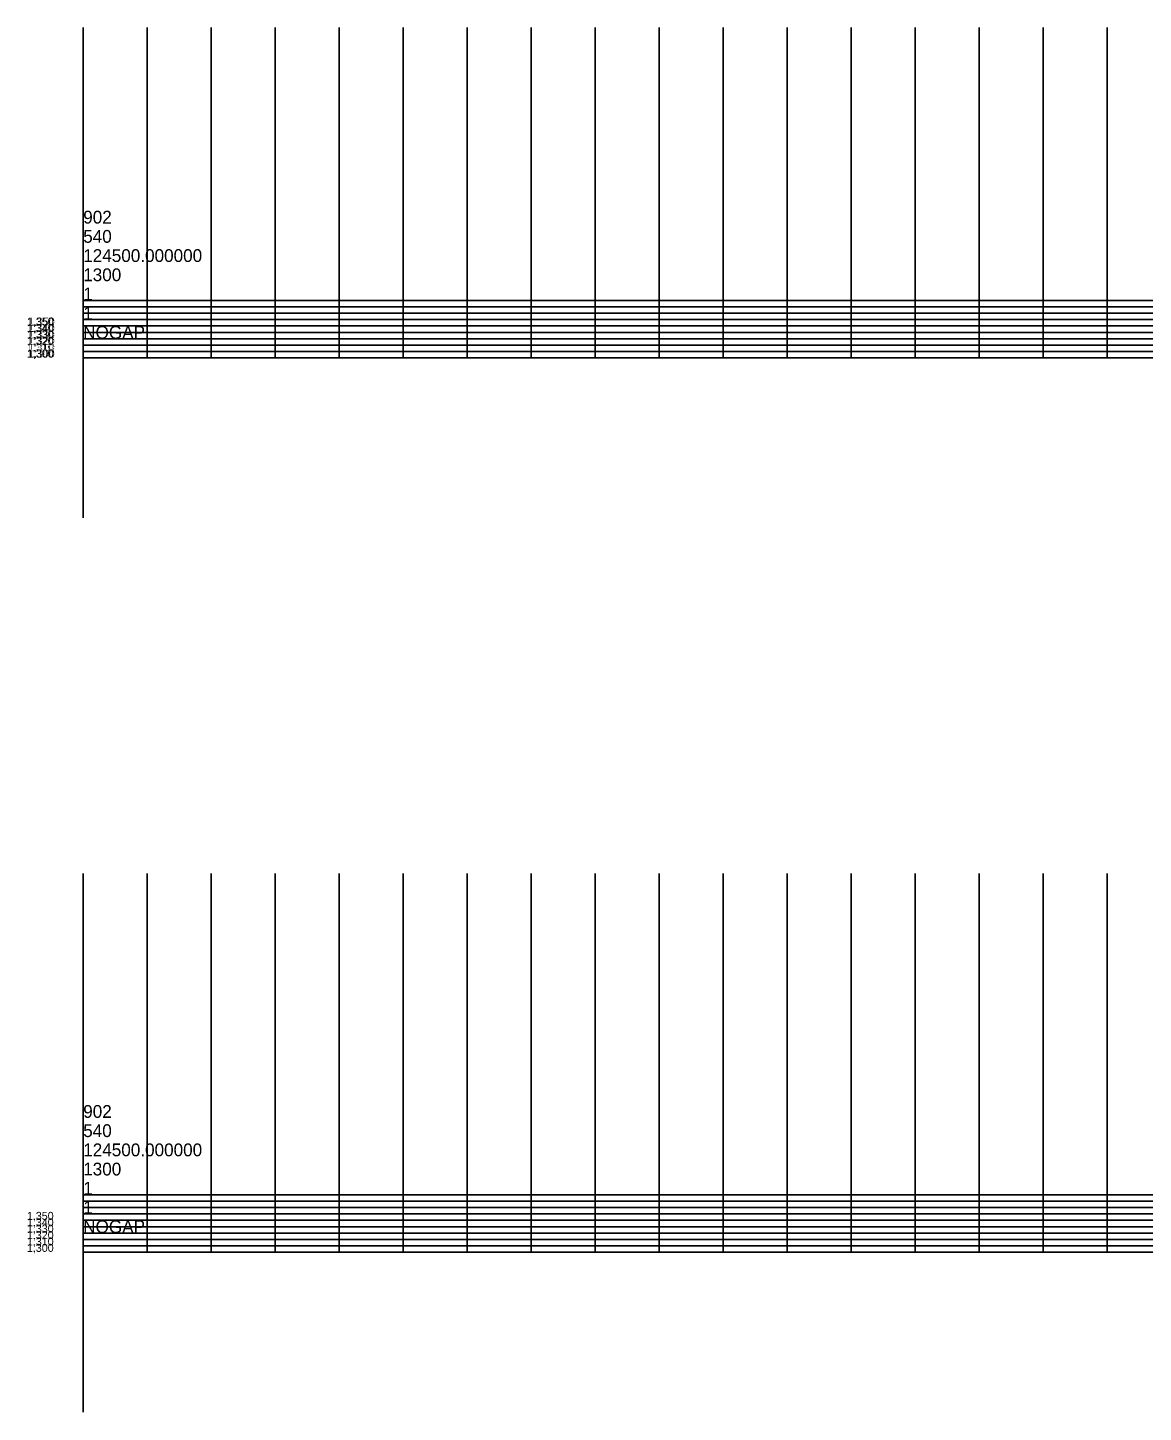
# Model space of a CAD drawing. Extents: x 680639 to 702326, y 743523 to 756592.
# Drawn here: x 680639 to 682382, y 743527 to 745690 of the extents above; entities that cross this region are included whole.
import ezdxf

# ---------------------------------------------------------------- set-up
doc = ezdxf.new("R2010")
doc.units = 0
doc.layers.add('Default', color=7, linetype='Continuous')
doc.layers.add('R_Grid', color=7, linetype='Continuous')

msp = doc.modelspace()

# ---------------------------------------------------------------- linework, layer by layer
at = {"layer": 'Default'}
for p, q in [((680725.7, 745174), (680725.7, 745424)), ((680725.7, 745174), (702325.7, 745174)), ((680725.7, 745174), (680725.7, 744924)), ((680725.7, 743776.7), (680725.7, 744026.7)), ((680725.7, 743776.7), (702325.7, 743776.7)), ((680725.7, 743776.7), (680725.7, 743526.7))]:
    msp.add_line(p, q, dxfattribs=at)
at = {"layer": 'R_Grid'}
for p, q in [((680725.7, 745174), (680725.7, 745690.1)), ((680825.7, 745174), (680825.7, 745690.1)), ((680925.7, 745174), (680925.7, 745690.1)), ((681025.7, 745174), (681025.7, 745690.1)), ((681125.7, 745174), (681125.7, 745690.1)), ((681225.7, 745174), (681225.7, 745690.1)), ((681325.7, 745174), (681325.7, 745690.1)), ((681425.7, 745174), (681425.7, 745690.1)), ((681525.7, 745174), (681525.7, 745690.1)), ((681625.7, 745174), (681625.7, 745690.1)), ((681725.7, 745174), (681725.7, 745690.1)), ((681825.7, 745174), (681825.7, 745690.1)), ((681925.7, 745174), (681925.7, 745690.1)), ((682025.7, 745174), (682025.7, 745690.1)), ((682125.7, 745174), (682125.7, 745690.1)), ((682225.7, 745174), (682225.7, 745690.1)), ((682325.7, 745174), (682325.7, 745690.1)), ((680725.7, 745264), (695445.5, 745264)), ((680725.7, 745254), (695445.5, 745254)), ((680725.7, 745244), (695445.5, 745244)), ((680725.7, 745234), (695445.5, 745234)), ((680725.7, 745224), (695445.5, 745224)), ((680725.7, 745214), (695445.5, 745214)), ((680725.7, 745204), (695445.5, 745204)), ((680725.7, 745194), (695445.5, 745194)), ((680725.7, 745184), (695445.5, 745184)), ((680725.7, 745174), (695445.5, 745174)), ((680725.7, 743776.7), (680725.7, 744368.3)), ((680825.7, 743776.7), (680825.7, 744368.3)), ((680925.7, 743776.7), (680925.7, 744368.3)), ((681025.7, 743776.7), (681025.7, 744368.3)), ((681125.7, 743776.7), (681125.7, 744368.3)), ((681225.7, 743776.7), (681225.7, 744368.3)), ((681325.7, 743776.7), (681325.7, 744368.3)), ((681425.7, 743776.7), (681425.7, 744368.3)), ((681525.7, 743776.7), (681525.7, 744368.3)), ((681625.7, 743776.7), (681625.7, 744368.3)), ((681725.7, 743776.7), (681725.7, 744368.3)), ((681825.7, 743776.7), (681825.7, 744368.3)), ((681925.7, 743776.7), (681925.7, 744368.3)), ((682025.7, 743776.7), (682025.7, 744368.3)), ((682125.7, 743776.7), (682125.7, 744368.3)), ((682225.7, 743776.7), (682225.7, 744368.3)), ((682325.7, 743776.7), (682325.7, 744368.3)), ((680725.7, 743866.7), (694315.6, 743866.7)), ((680725.7, 743856.7), (694315.6, 743856.7)), ((680725.7, 743846.7), (694315.6, 743846.7)), ((680725.7, 743836.7), (694315.6, 743836.7)), ((680725.7, 743826.7), (694315.6, 743826.7)), ((680725.7, 743816.7), (694315.6, 743816.7)), ((680725.7, 743806.7), (694315.6, 743806.7)), ((680725.7, 743796.7), (694315.6, 743796.7)), ((680725.7, 743786.7), (694315.6, 743786.7)), ((680725.7, 743776.7), (694315.6, 743776.7))]:
    msp.add_line(p, q, dxfattribs=at)

# ---------------------------------------------------------------- texts
at = {"layer": 'Default'}
for s, height, p in [('902', 20, (680725.7, 745384)), ('540', 20, (680725.7, 745354)), ('124500.000000', 20, (680725.7, 745324)), ('1300', 20, (680725.7, 745294)), ('1', 20, (680725.7, 745264)), ('1', 20, (680725.7, 745234)), ('1,350', 12.5, (680637.8, 745224.6)), ('1,350', 12.5, (680637.7, 745224.6)), ('1,340', 12.5, (680637.8, 745214.6)), ('1,340', 12.5, (680637.7, 745214.6)), ('1,350', 12.5, (680637.8, 745224.6)), ('1,340', 12.5, (680637.8, 745214.6)), ('1,350', 12.5, (680637.9, 745224.6)), ('1,340', 12.5, (680637.9, 745214.6)), ('1,350', 12.5, (680638, 745224.6)), ('1,340', 12.5, (680638, 745214.6)), ('1,350', 12.5, (680638.1, 745224.6)), ('1,340', 12.5, (680638.1, 745214.6)), ('1,350', 12.5, (680638.2, 745224.6)), ('1,350', 12.5, (680638.3, 745224.6)), ('1,340', 12.5, (680638.2, 745214.6)), ('1,340', 12.5, (680638.3, 745214.6)), ('1,350', 12.5, (680638.3, 745224.6)), ('1,340', 12.5, (680638.3, 745214.6)), ('1,350', 12.5, (680638.4, 745224.6)), ('1,340', 12.5, (680638.4, 745214.6)), ('1,350', 12.5, (680638.5, 745224.6)), ('1,340', 12.5, (680638.5, 745214.6)), ('1,350', 12.5, (680638.6, 745224.6)), ('1,340', 12.5, (680638.6, 745214.6)), ('1,350', 12.5, (680638.7, 745224.6)), ('1,350', 12.5, (680638.8, 745224.6)), ('1,340', 12.5, (680638.7, 745214.6)), ('1,340', 12.5, (680638.8, 745214.6)), ('1,350', 12.5, (680638.8, 745224.6)), ('1,340', 12.5, (680638.8, 745214.6)), ('1,350', 12.5, (680638.9, 745224.6)), ('1,340', 12.5, (680638.9, 745214.6)), ('1,350', 12.5, (680639, 745224.6)), ('1,340', 12.5, (680639, 745214.6)), ('1,350', 12.5, (680639.1, 745224.6)), ('1,340', 12.5, (680639.1, 745214.6)), ('1,350', 12.5, (680639.2, 745224.6)), ('1,350', 12.5, (680639.3, 745224.6)), ('1,340', 12.5, (680639.2, 745214.6)), ('1,340', 12.5, (680639.3, 745214.6)), ('1,330', 12.5, (680637.8, 745204.6)), ('1,330', 12.5, (680637.7, 745204.6)), ('1,320', 12.5, (680637.8, 745194.6)), ('1,320', 12.5, (680637.7, 745194.6)), ('1,330', 12.5, (680637.8, 745204.6)), ('1,320', 12.5, (680637.8, 745194.6)), ('1,330', 12.5, (680637.9, 745204.6)), ('1,320', 12.5, (680637.9, 745194.6)), ('1,330', 12.5, (680638, 745204.6)), ('1,320', 12.5, (680638, 745194.6)), ('1,330', 12.5, (680638.1, 745204.6)), ('1,320', 12.5, (680638.1, 745194.6)), ('1,330', 12.5, (680638.2, 745204.6)), ('1,330', 12.5, (680638.3, 745204.6)), ('1,320', 12.5, (680638.2, 745194.6)), ('1,320', 12.5, (680638.3, 745194.6)), ('1,330', 12.5, (680638.3, 745204.6)), ('1,320', 12.5, (680638.3, 745194.6)), ('1,330', 12.5, (680638.4, 745204.6)), ('1,320', 12.5, (680638.4, 745194.6)), ('1,330', 12.5, (680638.5, 745204.6)), ('1,320', 12.5, (680638.5, 745194.6)), ('1,330', 12.5, (680638.6, 745204.6)), ('1,320', 12.5, (680638.6, 745194.6)), ('1,330', 12.5, (680638.7, 745204.6)), ('1,330', 12.5, (680638.8, 745204.6)), ('1,320', 12.5, (680638.7, 745194.6)), ('1,320', 12.5, (680638.8, 745194.6)), ('1,330', 12.5, (680638.8, 745204.6)), ('1,320', 12.5, (680638.8, 745194.6)), ('1,330', 12.5, (680638.9, 745204.6)), ('1,320', 12.5, (680638.9, 745194.6)), ('1,330', 12.5, (680639, 745204.6)), ('1,320', 12.5, (680639, 745194.6)), ('1,330', 12.5, (680639.1, 745204.6)), ('1,320', 12.5, (680639.1, 745194.6)), ('1,330', 12.5, (680639.2, 745204.6)), ('1,330', 12.5, (680639.3, 745204.6)), ('1,320', 12.5, (680639.2, 745194.6)), ('1,320', 12.5, (680639.3, 745194.6)), ('NOGAP', 20, (680725.7, 745204)), ('1,310', 12.5, (680637.8, 745184.6)), ('1,310', 12.5, (680637.7, 745184.6)), ('1,300', 12.5, (680637.8, 745174.6)), ('1,300', 12.5, (680637.7, 745174.6)), ('1,310', 12.5, (680637.8, 745184.6)), ('1,300', 12.5, (680637.8, 745174.6)), ('1,310', 12.5, (680637.9, 745184.6)), ('1,300', 12.5, (680637.9, 745174.6)), ('1,310', 12.5, (680638, 745184.6)), ('1,300', 12.5, (680638, 745174.6)), ('1,310', 12.5, (680638.1, 745184.6)), ('1,300', 12.5, (680638.1, 745174.6)), ('1,310', 12.5, (680638.2, 745184.6)), ('1,310', 12.5, (680638.3, 745184.6)), ('1,300', 12.5, (680638.2, 745174.6)), ('1,300', 12.5, (680638.3, 745174.6)), ('1,310', 12.5, (680638.3, 745184.6)), ('1,300', 12.5, (680638.3, 745174.6)), ('1,310', 12.5, (680638.4, 745184.6)), ('1,300', 12.5, (680638.4, 745174.6)), ('1,310', 12.5, (680638.5, 745184.6)), ('1,300', 12.5, (680638.5, 745174.6)), ('1,310', 12.5, (680638.6, 745184.6)), ('1,300', 12.5, (680638.6, 745174.6)), ('1,310', 12.5, (680638.7, 745184.6)), ('1,310', 12.5, (680638.8, 745184.6)), ('1,300', 12.5, (680638.7, 745174.6)), ('1,300', 12.5, (680638.8, 745174.6)), ('1,310', 12.5, (680638.8, 745184.6)), ('1,300', 12.5, (680638.8, 745174.6)), ('1,310', 12.5, (680638.9, 745184.6)), ('1,300', 12.5, (680638.9, 745174.6)), ('1,310', 12.5, (680639, 745184.6)), ('1,300', 12.5, (680639, 745174.6)), ('1,310', 12.5, (680639.1, 745184.6)), ('1,300', 12.5, (680639.1, 745174.6)), ('1,310', 12.5, (680639.2, 745184.6)), ('1,310', 12.5, (680639.3, 745184.6)), ('1,300', 12.5, (680639.2, 745174.6)), ('1,300', 12.5, (680639.3, 745174.6)), ('902', 20, (680725.7, 743986.7)), ('540', 20, (680725.7, 743956.7)), ('124500.000000', 20, (680725.7, 743926.7)), ('1300', 20, (680725.7, 743896.7)), ('1', 20, (680725.7, 743866.7)), ('1', 20, (680725.7, 743836.7)), ('1,350', 12.5, (680637.7, 743827.3)), ('1,340', 12.5, (680637.7, 743817.3)), ('1,340', 12.5, (680637.7, 743817.3)), ('NOGAP', 20, (680725.7, 743806.7)), ('1,330', 12.5, (680637.7, 743807.3)), ('1,330', 12.5, (680637.7, 743807.3)), ('1,320', 12.5, (680637.7, 743797.3)), ('1,320', 12.5, (680637.7, 743797.3)), ('1,310', 12.5, (680637.7, 743787.3)), ('1,310', 12.5, (680637.7, 743787.3)), ('1,300', 12.5, (680637.7, 743777.3)), ('1,300', 12.5, (680637.7, 743777.3))]:
    msp.add_text(s, height=height, dxfattribs=at).set_placement(p)

doc.saveas('drawing.dxf')
